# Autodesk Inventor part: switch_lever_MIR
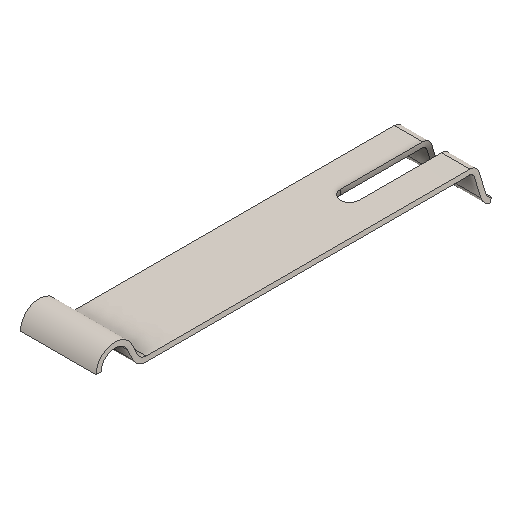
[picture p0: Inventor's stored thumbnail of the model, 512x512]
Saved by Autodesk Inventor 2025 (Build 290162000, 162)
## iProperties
Created: 2025-10
Part Number: switch_lever_MIR
Material: Generico
Document SubType Name: Modeling
Designer: Ryzen5700u
Density: 1 g/cm^3
Appearance: Default
Author: Ryzen5700u
Revision Number: ANY
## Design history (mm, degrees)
derived "switch_lever.ipt"
feature "Solido1::switch_lever.ipt" dims "d0" = 10
tag "Lavorazione contrassegno1"
node "Solido1"
